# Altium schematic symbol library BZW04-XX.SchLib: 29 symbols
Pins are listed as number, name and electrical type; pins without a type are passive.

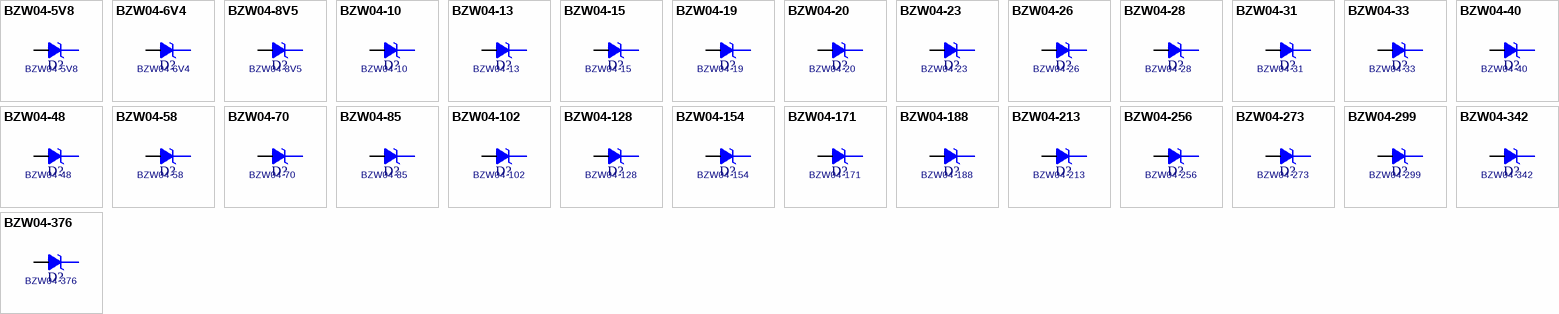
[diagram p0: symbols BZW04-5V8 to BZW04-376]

## BZW04-5V8
designator D?
footprint ST_DO15
pins: 1 K, 2 A

## BZW04-6V4
designator D?
footprint ST_DO15
pins: 1 K, 2 A

## BZW04-8V5
designator D?
footprint ST_DO15
pins: 1 K, 2 A

## BZW04-10
designator D?
footprint ST_DO15
pins: 1 K, 2 A

## BZW04-13
designator D?
footprint ST_DO15
pins: 1 K, 2 A

## BZW04-15
designator D?
footprint ST_DO15
pins: 1 K, 2 A

## BZW04-19
designator D?
footprint ST_DO15
pins: 1 K, 2 A

## BZW04-20
designator D?
footprint ST_DO15
pins: 1 K, 2 A

## BZW04-23
designator D?
footprint ST_DO15
pins: 1 K, 2 A

## BZW04-26
designator D?
footprint ST_DO15
pins: 1 K, 2 A

## BZW04-28
designator D?
footprint ST_DO15
pins: 1 K, 2 A

## BZW04-31
designator D?
footprint ST_DO15
pins: 1 K, 2 A

## BZW04-33
designator D?
footprint ST_DO15
pins: 1 K, 2 A

## BZW04-40
designator D?
footprint ST_DO15
pins: 1 K, 2 A

## BZW04-48
designator D?
footprint ST_DO15
pins: 1 K, 2 A

## BZW04-58
designator D?
footprint ST_DO15
pins: 1 K, 2 A

## BZW04-70
designator D?
footprint ST_DO15
pins: 1 K, 2 A

## BZW04-85
designator D?
footprint ST_DO15
pins: 1 K, 2 A

## BZW04-102
designator D?
footprint ST_DO15
pins: 1 K, 2 A

## BZW04-128
designator D?
footprint ST_DO15
pins: 1 K, 2 A

## BZW04-154
designator D?
footprint ST_DO15
pins: 1 K, 2 A

## BZW04-171
designator D?
footprint ST_DO15
pins: 1 K, 2 A

## BZW04-188
designator D?
footprint ST_DO15
pins: 1 K, 2 A

## BZW04-213
designator D?
footprint ST_DO15
pins: 1 K, 2 A

## BZW04-256
designator D?
footprint ST_DO15
pins: 1 K, 2 A

## BZW04-273
designator D?
footprint ST_DO15
pins: 1 K, 2 A

## BZW04-299
designator D?
footprint ST_DO15
pins: 1 K, 2 A

## BZW04-342
designator D?
footprint ST_DO15
pins: 1 K, 2 A

## BZW04-376
designator D?
footprint ST_DO15
pins: 1 K, 2 A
